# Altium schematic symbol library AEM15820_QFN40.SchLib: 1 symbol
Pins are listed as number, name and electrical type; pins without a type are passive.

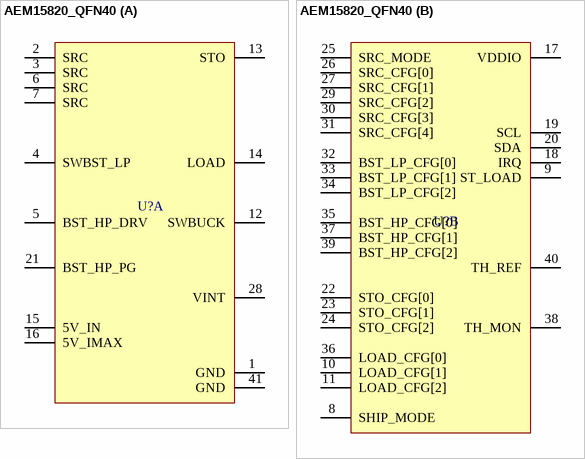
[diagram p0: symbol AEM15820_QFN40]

## AEM15820_QFN40
designator U?  (value not drawn)
AEM15820 QFN40
footprint QFN40_5x5mm_pitch0.4mm_ASE_98A0040QN185 (QFN40 body 5x5mm pitch 0.4mm Manufacturer ASE)
part A pins: 1 GND, 2 SRC, 3 SRC, 4 SWBST_LP, 5 BST_HP_DRV, 6 SRC, 7 SRC, 12 SWBUCK, 13 STO, 14 LOAD, 15 5V_IN, 16 5V_IMAX, 21 BST_HP_PG, 28 VINT, 41 GND
part B pins: 8 SHIP_MODE, 9 ST_LOAD, 10 LOAD_CFG[1], 11 LOAD_CFG[2], 17 VDDIO, 18 IRQ, 19 SCL, 20 SDA, 22 STO_CFG[0], 23 STO_CFG[1], 24 STO_CFG[2], 25 SRC_MODE, 26 SRC_CFG[0], 27 SRC_CFG[1], 29 SRC_CFG[2], 30 SRC_CFG[3], 31 SRC_CFG[4], 32 BST_LP_CFG[0], 33 BST_LP_CFG[1], 34 BST_LP_CFG[2], 35 BST_HP_CFG[0], 36 LOAD_CFG[0], 37 BST_HP_CFG[1], 38 TH_MON, 39 BST_HP_CFG[2], 40 TH_REF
